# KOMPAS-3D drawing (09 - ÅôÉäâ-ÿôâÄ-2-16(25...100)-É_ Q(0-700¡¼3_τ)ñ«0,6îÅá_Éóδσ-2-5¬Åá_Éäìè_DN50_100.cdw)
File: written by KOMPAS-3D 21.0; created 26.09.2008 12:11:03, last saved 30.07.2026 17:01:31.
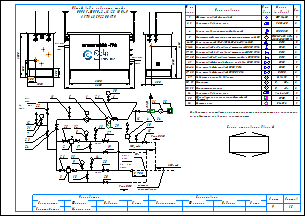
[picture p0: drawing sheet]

Sheets 1-2: A3, landscape

Document properties: Наименование: Макро:21; Автор: RaskoAdmin; Форматы листов документа: 2xA3; Полное имя файла: \\UR38nt01\Departments\КТО\КБ ПУРДГ\Заявки\Прайс-лист на типовые шкафы ГРПШ\ПУРДГ_стандарт_30_04_2026\ПУРДГ с РДНК\ПУРДГ-ШУГО-2-16(25...100)-Р_ Q(0-700нм3_ч)до0,6МПа_Рвых-2-5кПа_РДНК_DN50_100.cdw

Title block, sheet 1: Наименование: Пункт учета газа / ПУГ-Ш-400-Р / ЛГТИ.485922.001ТУ; designation: ЛГТИ.03.4411141; sheet number: 1; Количество листов документа: 2; organisation: ООО "ЭЛЬСТЕР Газэлектроника"; Форматы листов документа: A3; stored path: C:\Рабочие документы\Компас\ПУГ\Схема.cdw; Разработал: Устинов; Проверил: Кошкин; Утвердил: Кошкин
Title block, sheet 2: sheet number: 2; stored path: D:\Рабочие документы\Заявки\ПУРДГ\ПУРДГ-ШУЭО-2-100-Р 4411220.cdw; designation, second copy: ЛГТИ.03.4411141-

Views: Вид 1, Вид 2
Referenced files: wcvoit.frw
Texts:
  Normal
  Общий вид и габариты шкафа
  ПУРДГ-ШУГО-2-16(25...100)-Р
  DN100
  Выход газа
  DN50
  Вход газа
  logo-rasko-ge.png
  DN 1
  местное
  сопротивление
  Римп DN15
  Римп DN20
  Выход
  газа
  Р=     кПа
  Вход
  Р=       МПа
  PDI
  № на
  схеме
  Усл.
  обозн.
  Марка
  (модель)
  Кол.
  Фильтр газовый фланцевый
  ФГ 16-50
  Регулятор давления газа
  РДНК-50
  Клапан предохранительный сбросной
  КПС DN20
  Измерительный комплекс с ротационным счетчиком Ду50
  СГ-ЭК-Р-(0,2...2,0)-
  Кран кнопочный VE-РАСКО-НЗ-1,6-G1/2-М20
  DN15
  Кран шаровой "под приварку" штуцерный DN20 PN16
  DN20
  Кран шаровой "под приварку" штуцерный DN15 PN16
  Кран шаровой "под приварку" штуцерный п/п DN15 PN16
  Кран шаровой фланцевый с мех. приводом DN50 PN16
  Кран шаровой фланцевый DN50 PN16
  Кран шаровой фланцевый DN100 PN16
  Индикатор перепада давления
  Манометр
  Манометр-напоромер
  Обогреватель газогорелочный шкафной
  (Эльтон")
  Счетчик газа
  Delta 15
  0...     МПа
  0...     кПа
  Venio-A-15
  ОГШН
  BK-G1,6
  Схема открывания дверей
  Предприятие изготовитель может заменять комплектующие на аналогичные,
  не ухудшающие заявленных характеристик.
  Должность
  Конструктор
  Фамилия
  Подпись
  Дата
  Согласовано
  Максимкин
  Лист
  Листов
  POLYLINE_STYLE_0.18_RGB_0_0_0
  POLYLINE_STYLE_0.50_RGB_0_0_0
  POLYLINE_STYLE_0.34_RGB_0_0_0
  PHANTOM_RGB_0_0_0_SC_1_THICK_0.18
  K5LT_THIN_RGB_0_0_0_THICK_0.18
  K5LT32769_RGB_0_0_0_THICK_0.18
  K5LT12_RGB_0_0_0_SC_1_THICK_0.18
  K5LT_DASHED_RGB_0_0_0_SC_1_THICK_0.18
  ACISOTGL_RGB_0_0_0_SC_0.8_THICK_0.25
  CONTINUOUS_RGB_0_127_31_THICK_0.3
  CONTINUOUS_RGB_0_0_255_THICK_0.35
  CONTINUOUS_RGB_255_0_0_THICK_0.35
  POLYLINE_STYLE_0.25_RGB_0_0_0
  CONTINUOUS_RGB_0_0_0_THICK_0.5
  POLYLINE_STYLE_0.35_RGB_0_0_255
  CONTINUOUS_RGB_0_0_0_THICK_0.4
  CONTINUOUS_RGB_0_0_0_THICK_0.35
  НЕВИДИМАЯ_RGB_0_0_0_SC_0.3_THICK_0.25
  СONTINUOUS_RGB_0_0_0_THICK_0.25
  ОСЕВАЯ2_RGB_248_153_30_SC_0.3_THICK_0.25
  Без оформления
Dimensions and other numbers on the sheet: 1; 1500; 250; 300; 1050; 550; 305; 2300; 4130; 2000; 2600; 5,,,7DN 1; 7; 31; 12; 22; 23; 24; 11; 5; 21; 6; 30; 25; 32; 8; 2; 17; 13; 27; 19; 4; 10; 15; 26; 33; 9; 3; 18; 14; 28; 20; 29; 2, 3; 6-10; 11-16; 17, 18; 19, 20; 22-26; 27, 28; 30, 31; 32, 33; 34; 35; 36; 16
